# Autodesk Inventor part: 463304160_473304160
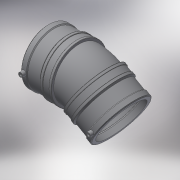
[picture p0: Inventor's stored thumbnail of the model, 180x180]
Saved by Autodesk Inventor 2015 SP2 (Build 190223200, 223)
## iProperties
Created: 2017-06
Part Number: 463304160_473304160
Material: Generic
Description: PLASSON 30° LIGHTFIT ELBOW 160
Document SubType Name: Modeling
Designer: KIM
Mass: 12693.1 g
Surface Area: 10598.3 cm^2
Volume: 12693.1 cm^3
Density: 1 g/cm^3
Appearance: Default
Author: KIM
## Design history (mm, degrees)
derived "473304.ipt"
feature "Solid1::473304.ipt"
tag "TaggingFeature1"
body "Solid1"
other parameters: "d14" = 17.6296, "d19" = 3.52592, "d20" = 168 deg, "d22" = 189.14, "d23" = 193, "d24" = 183.4658, "d25" = 135 deg, "d26" = 120.8, "d29" = 106, "d43" = 135 deg, "d45" = 12.08, "d47" = 9.06, "d48" = 189.14, "d49" = 193, "d50" = 0.965, "d51" = 94.57, "d52" = 150 deg, "d53" = 302, "d54" = 21.56, "d55" = 107.8, "d56" = 152, "d57" = 68.6, "d58" = 106, "d59" = 15, "d61" = 5 deg, "d63" = 4, "d64" = 14, "d65" = 0, "d67" = 150 deg, "d69" = 176, "d71" = 98, "d72" = 0, "d73" = 98, "d74" = 0, "d75" = 3, "d76" = 0, "L_" = 302, "L_1" = 98, "D_" = 193, "A_" = 106, "d_2" = 12
